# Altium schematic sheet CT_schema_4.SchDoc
size 186 x 134 mm
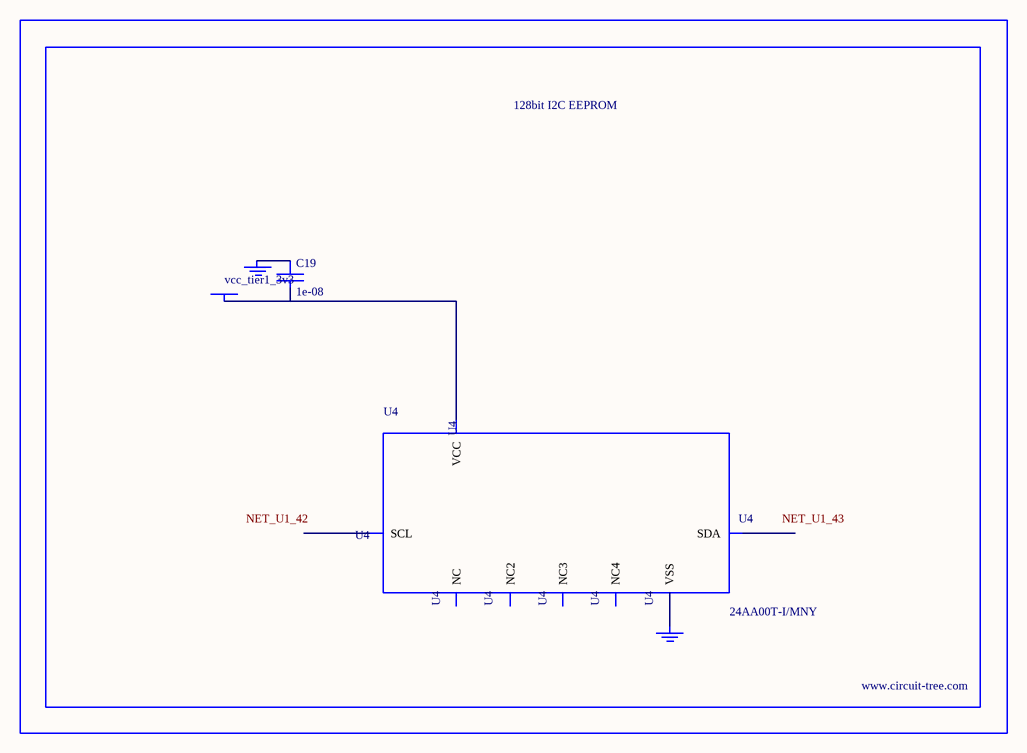
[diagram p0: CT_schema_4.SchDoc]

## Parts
BORDER3  (no value)
C19  1e-08  [C0402]
GND_INSTANCE_3_0  (no value)
GND_INSTANCE_3_1  (no value)
POWER_INSTANCE_3_0  vcc_tier1_3v3
U4  24AA00T-I/MNY  [TDFN-8/6MM]

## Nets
NetC19_1: C19.1 GND_INSTANCE_3_0.0(GND)
NetC19_2: C19.2 POWER_INSTANCE_3_0.0(PWR) U4.8(VCC)
NetGND_INSTANCE_3_1_0: GND_INSTANCE_3_1.0(GND) U4.4(VSS)

Not connected (* = marked no-connect by the designer): U4 1(NC) 2(NC2) 3(NC3) 5(SDA) 6(SCL) 7(NC4)

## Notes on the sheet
- Labels drawn without touching a wire or pin: NET_U1_42, NET_U1_43

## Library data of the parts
BORDER3 = BORDER_PAGE3
C19 = C0402C103K3RAC
GND_INSTANCE_3_0 GND_INSTANCE_3_1 = GND
POWER_INSTANCE_3_0 = PWR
